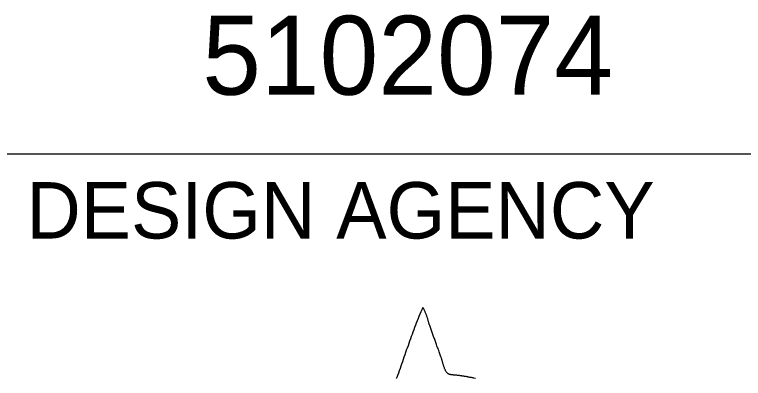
# Model space of a CAD drawing. Extents: x 0 to 45.3, y 0 to 22.
# Drawn here: x 32.029 to 33.322, y 4.602 to 5.247 of the extents above; entities that cross this region are included whole.
import ezdxf

# ---------------------------------------------------------------- set-up
doc = ezdxf.new("R2010")
doc.units = 0
for name, color, linetype in [('SH_Border', 7, 'Continuous'), ('SH_Data', 7, 'Continuous'), ('SH_Text', 7, 'Continuous')]:
    doc.layers.add(name, color=color, linetype=linetype)

msp = doc.modelspace()

# ---------------------------------------------------------------- linework, layer by layer
at = {"layer": 'SH_Border'}
msp.add_line((32, 5), (33.5, 5), dxfattribs=at)
at = {"layer": 'SH_Text'}
for points in [[(32.7532, 4.7277), (32.7515, 4.7238), (32.7498, 4.7199), (32.7481, 4.716), (32.7466, 4.712), (32.745, 4.708), (32.7434, 4.7041), (32.7418, 4.7001), (32.7403, 4.6961), (32.7387, 4.6921), (32.7372, 4.6881), (32.7357, 4.6841), (32.7342, 4.6801), (32.7328, 4.676), (32.7313, 4.672), (32.7298, 4.668), (32.7284, 4.6639), (32.7271, 4.6599), (32.7256, 4.6558), (32.7241, 4.6518), (32.7227, 4.6478), (32.7214, 4.6436), (32.7199, 4.6396), (32.7184, 4.6355), (32.7171, 4.6315), (32.7157, 4.6275), (32.7142, 4.6235), (32.7129, 4.6194), (32.7114, 4.6154), (32.71, 4.6114), (32.7085, 4.6074), (32.707, 4.6035)], [(32.7656, 4.6959), (32.7652, 4.6969), (32.7649, 4.6978), (32.7646, 4.6988), (32.7643, 4.6998), (32.764, 4.7009), (32.7637, 4.702), (32.7633, 4.7031), (32.7631, 4.7041), (32.7627, 4.7051), (32.7623, 4.7063), (32.7621, 4.7074), (32.7617, 4.7085), (32.7614, 4.7096), (32.761, 4.7107), (32.7606, 4.7118), (32.7603, 4.7129), (32.7599, 4.714), (32.7595, 4.7151), (32.7592, 4.7161), (32.7587, 4.7172), (32.7583, 4.7182), (32.7578, 4.7193), (32.7575, 4.7203), (32.757, 4.7214), (32.7565, 4.7223), (32.756, 4.7233), (32.7555, 4.7242), (32.7549, 4.7251), (32.7545, 4.726), (32.7538, 4.7268), (32.7532, 4.7277)], [(32.7856, 4.6404), (32.785, 4.6422), (32.7844, 4.644), (32.7837, 4.6457), (32.7831, 4.6475), (32.7823, 4.6493), (32.7817, 4.6512), (32.781, 4.6529), (32.7804, 4.6547), (32.7797, 4.6565), (32.7791, 4.6582), (32.7783, 4.66), (32.7777, 4.6618), (32.777, 4.6637), (32.7764, 4.6654), (32.7758, 4.6672), (32.7751, 4.669), (32.7745, 4.6708), (32.7739, 4.6725), (32.7731, 4.6743), (32.7725, 4.6761), (32.7719, 4.678), (32.7712, 4.6797), (32.7706, 4.6815), (32.77, 4.6833), (32.7694, 4.6851), (32.7686, 4.6869), (32.768, 4.6886), (32.7674, 4.6904), (32.7668, 4.6923), (32.7662, 4.6941), (32.7656, 4.6959)], [(32.7979, 4.6106), (32.7973, 4.6112), (32.7966, 4.6118), (32.796, 4.6124), (32.7954, 4.6131), (32.7949, 4.6138), (32.7943, 4.6147), (32.7939, 4.6156), (32.7934, 4.6165), (32.7929, 4.6175), (32.7925, 4.6186), (32.792, 4.6195), (32.7917, 4.6206), (32.7913, 4.6217), (32.7908, 4.6228), (32.7905, 4.6239), (32.7901, 4.6251), (32.7899, 4.6262), (32.7895, 4.6274), (32.7891, 4.6285), (32.7889, 4.6296), (32.7885, 4.6308), (32.7882, 4.6319), (32.7879, 4.633), (32.7877, 4.6341), (32.7873, 4.635), (32.7871, 4.636), (32.7868, 4.637), (32.7865, 4.638), (32.7862, 4.6388), (32.786, 4.6396), (32.7856, 4.6404)], [(32.707, 4.6035), (32.7067, 4.6025), (32.7063, 4.6016)], [(32.8139, 4.6075), (32.8134, 4.6075), (32.8129, 4.6076), (32.8124, 4.6076), (32.8119, 4.6076), (32.8114, 4.6078), (32.8108, 4.6078), (32.8103, 4.6078), (32.8097, 4.6078), (32.8093, 4.6079), (32.8086, 4.6079), (32.808, 4.6079), (32.8076, 4.6079), (32.807, 4.608), (32.8063, 4.608), (32.8059, 4.6081), (32.8053, 4.6081), (32.8046, 4.6082), (32.8042, 4.6082), (32.8036, 4.6084), (32.8031, 4.6085), (32.8025, 4.6086), (32.802, 4.6087), (32.8015, 4.6089), (32.8009, 4.609), (32.8004, 4.6092), (32.7999, 4.6093), (32.7996, 4.6096), (32.7991, 4.6098), (32.7986, 4.6101), (32.7982, 4.6103), (32.7979, 4.6106)], [(32.8436, 4.6024), (32.8426, 4.6027), (32.8417, 4.6028), (32.8408, 4.603), (32.8398, 4.6033), (32.8388, 4.6034), (32.8379, 4.6036), (32.8369, 4.6038), (32.8359, 4.604), (32.835, 4.6041), (32.8341, 4.6044), (32.8331, 4.6045), (32.8322, 4.6047), (32.8312, 4.6049), (32.8302, 4.6051), (32.8293, 4.6052), (32.8283, 4.6055), (32.8273, 4.6056), (32.8263, 4.6057), (32.8254, 4.6059), (32.8244, 4.6061), (32.8234, 4.6062), (32.8225, 4.6063), (32.8215, 4.6065), (32.8205, 4.6067), (32.8196, 4.6068), (32.8186, 4.6069), (32.8177, 4.607), (32.8168, 4.6072), (32.8158, 4.6073), (32.8148, 4.6074), (32.8139, 4.6075)], [(32.8466, 4.6018), (32.8436, 4.6024)]]:
    msp.add_lwpolyline(points, dxfattribs=at)

# ---------------------------------------------------------------- texts
at = {"layer": 'SH_Data'}
for s, height, p in [('5102074', 0.14, (32.3621, 5.105)), ('DESIGN AGENCY', 0.1, (32.05, 4.85))]:
    msp.add_text(s, height=height, dxfattribs=at).set_placement(p)

doc.saveas('drawing.dxf')
